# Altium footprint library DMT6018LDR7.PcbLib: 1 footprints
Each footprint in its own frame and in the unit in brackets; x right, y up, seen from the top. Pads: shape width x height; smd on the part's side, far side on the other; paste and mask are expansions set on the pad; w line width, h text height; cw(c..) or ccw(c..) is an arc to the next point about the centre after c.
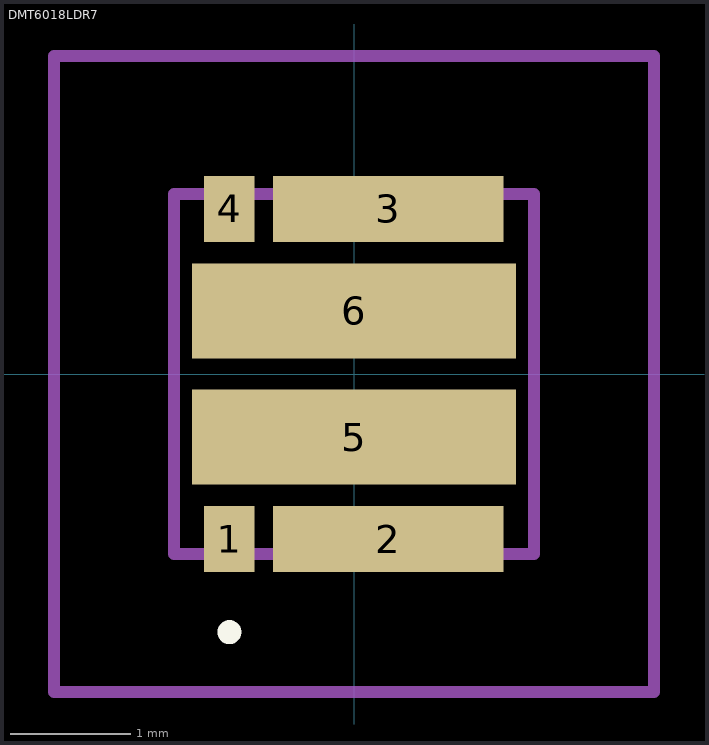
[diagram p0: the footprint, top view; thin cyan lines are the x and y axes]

## DMT6018LDR7 [mm]
pads (6):
  rect 0.42x0.55 smd: 1(-1.038,-1.375) 4(-1.038,1.375)
  rect 1.92x0.55 smd: 2(0.287,-1.375) 3(0.287,1.375)
  rect 2.7x0.79 smd: 5(0,-0.525) 6(0,0.525)
Top Overlay:
  lines w0.1: -1.038,-2.2 -1.038,-2.2 ; -1.038,-2.2 ccw(c-1.038,-2.15) -1.038,-2.1 ; -1.038,-2.2 cw(c-1.038,-2.15) -1.038,-2.1 ; -1.038,-2.1 -1.038,-2.1
Mechanical 15:
  lines w0.1: -1.5,-1.5 1.5,-1.5 1.5,1.5 -1.5,1.5 -1.5,-1.5
Mechanical 20:
  lines w0.1: -2.5,-2.65 2.5,-2.65 2.5,2.65 -2.5,2.65 -2.5,-2.65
